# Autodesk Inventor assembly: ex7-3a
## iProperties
Shininess: 3
Length Units: 11272
Angle Units: 11279
Time Units: 11290
Mass Units: 11286
Length Display Precision: 3
Angle Display Precision: 2
Compacted: True
Manager: Lebovitz
Company: Autodesk
Created: 2001-07
Part Number: ex7-3a
Document SubType Name: Assembly
Designer: The PD Team
Project: Inventor Samples
Density: 0.0
Volumn: 0.0
Area: 0.0
PropertySet Name: Model Information
Control State: 0
Master: False
Checked Out: False
Author: The PD team
Subject: Inventor Samples
Revision Number: A
